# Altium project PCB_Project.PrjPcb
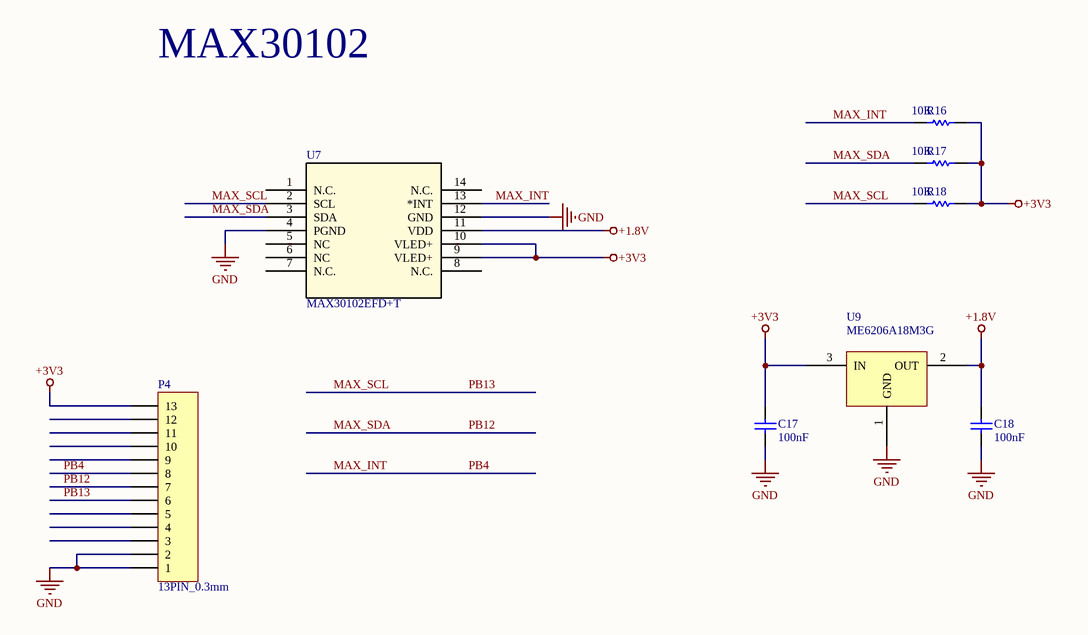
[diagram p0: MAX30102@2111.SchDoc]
1 sheet, 8 parts. Net scope: global (net labels, ports and power ports of the same name join across sheets).
Board file: MAX30102@2111.PcbDoc

## Sheet MAX30102@2111.SchDoc
size A4

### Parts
C17  100nF  [0402_C]
C18  100nF  [0402_C]
P4  13PIN_0.3mm  [FFC/FPC-13(6+7)-P0.3]
R16  10K  [0402]
R17  10K  [0402]
R18  10K  [0402]
U7  MAX30102EFD+T  [21-1048_F143A5+1_MXM-M]
U9  ME6206A18M3G  [SOT-23]

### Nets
+1.8V: C18.1 U7.11(VDD) U9.2(OUT)
+3V3: C17.1 P4.13 R16.1 R17.1 R18.1 U7.9(VLED+) U7.10(VLED+) U9.3(IN)
GND: C17.2 C18.2 P4.1 P4.2 U7.4(PGND) U7.12(GND) U9.1(GND)
MAX_INT: P4.8 R16.2 U7.13(*INT)  [also labelled PB4]
MAX_SCL: P4.6 R18.2 U7.2(SCL)  [also labelled PB13]
MAX_SDA: P4.7 R17.2 U7.3(SDA)  [also labelled PB12]

Not connected (* = marked no-connect by the designer): P4 3 4 5 9 10 11 12; U7 1(N.C.) 5(NC) 6(NC) 7(N.C.) 8(N.C.) 14(N.C.)

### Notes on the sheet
- MAX30102

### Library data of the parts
C17 C18 = Cap: Capacitor
P4 = Header 13: Header, 13-Pin
R16-R18 = Res1: Resistor
U7 = MAX30102EFD+T: No Description Available; SourceLibrary: Update_to_database_2021-01-29; Built_By: EMA_UL_Team; Vendor: Maxim Integrated Products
